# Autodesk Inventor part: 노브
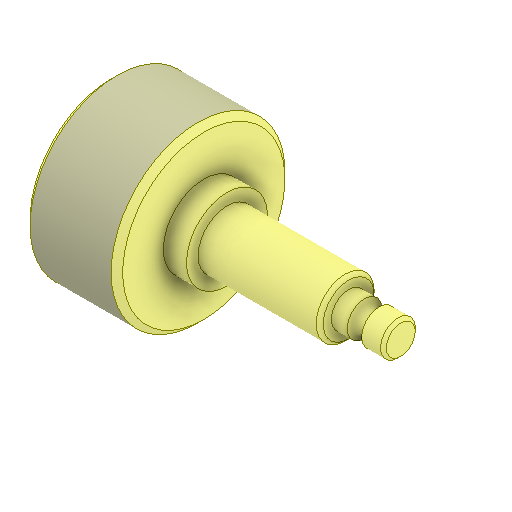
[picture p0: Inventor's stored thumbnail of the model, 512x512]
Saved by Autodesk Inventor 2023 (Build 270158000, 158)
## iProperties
Created: 2025-02
Part Number: 노브
Material: 강철, 탄소
Document SubType Name: Modeling
Designer: home
Density: 7.85 g/cm^3
Appearance: 기본값
Author: jhkim
Sending System: Autodesk Inventor 2025
Preprocessor: ST-DEVELOPER v20
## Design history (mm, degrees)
node "노브1"
node "솔리드2"
node "솔리드1"
